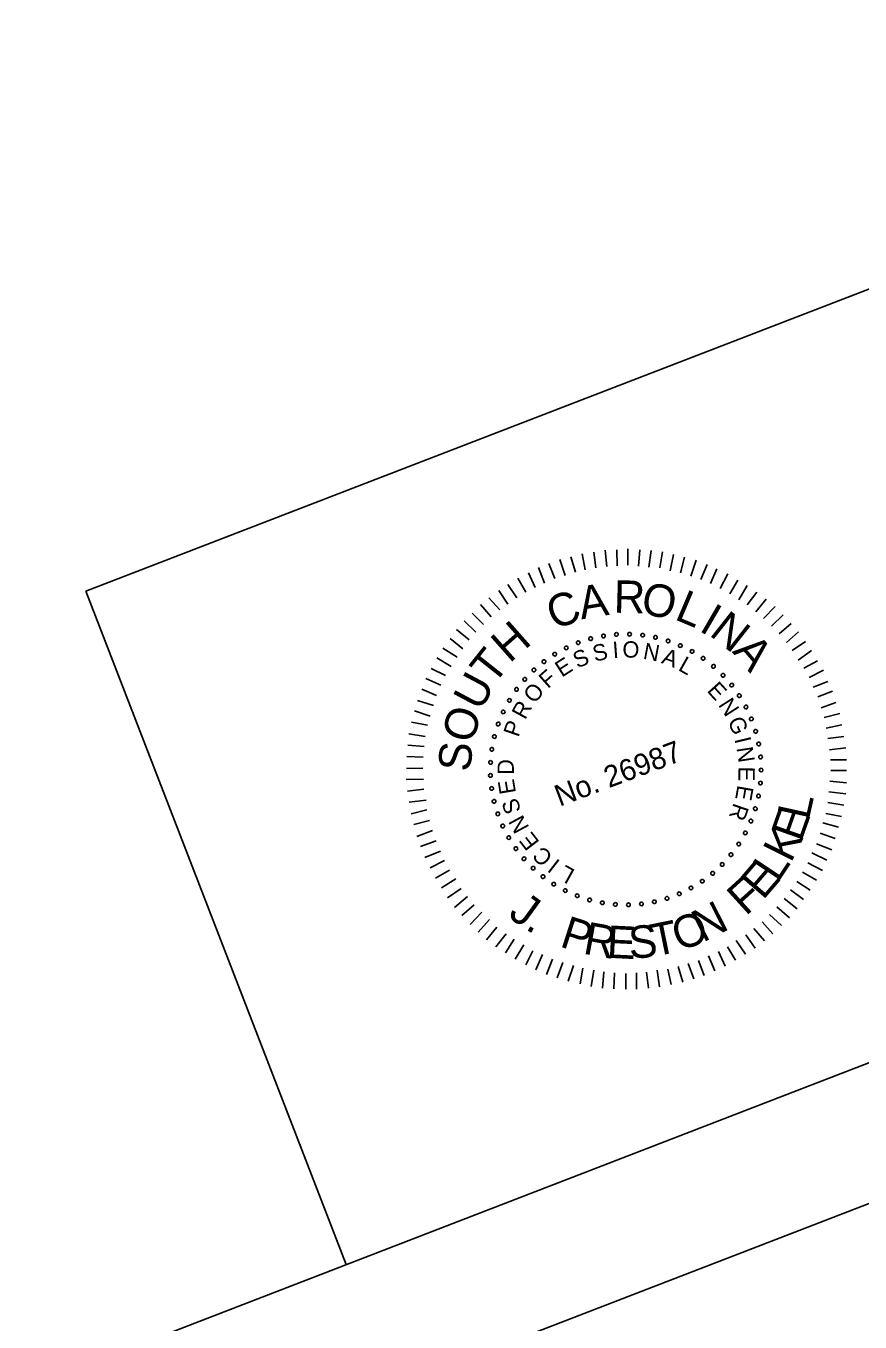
# Model space of a CAD drawing. Extents: x 1971188 to 1971603, y 795903 to 796238.
# Drawn here: x 1971464.12 to 1971495.88, y 795987.28 to 796036.66 of the extents above; entities that cross this region are included whole.
import ezdxf

# ---------------------------------------------------------------- set-up
doc = ezdxf.new("R2010")
doc.units = 0
for name, color, linetype in [('BR_BORDER LINES', 7, 'Continuous'), ('BR_TEXT', 7, 'Continuous'), ('Level 31', 7, 'Continuous')]:
    doc.layers.add(name, color=color, linetype=linetype)

msp = doc.modelspace()

# ---------------------------------------------------------------- linework, layer by layer
at = {"layer": 'BR_BORDER LINES'}
for p, q in [((1971282.272, 795914.531), (1971596.323, 796035.824)), ((1971466.4, 796015.126), (1971516.449, 796034.456)), ((1971476.308, 795989.472), (1971466.4, 796015.126))]:
    msp.add_line(p, q, dxfattribs=at)
at = {"layer": 'BR_TEXT'}
for p, q in [((1971485.419, 796015.944), (1971485.301, 796016.551)), ((1971485.824, 796016.014), (1971485.744, 796016.617)), ((1971486.245, 796016.063), (1971486.176, 796016.687)), ((1971486.627, 796016.097), (1971486.625, 796016.71)), ((1971487.042, 796016.115), (1971487.037, 796016.737)), ((1971487.44, 796016.082), (1971487.5, 796016.701)), ((1971487.838, 796016.048), (1971487.93, 796016.679)), ((1971488.255, 796016.013), (1971488.361, 796016.631)), ((1971484.254, 796015.606), (1971484.036, 796016.184)), ((1971484.656, 796015.73), (1971484.445, 796016.339)), ((1971485.043, 796015.848), (1971484.868, 796016.433)), ((1971488.653, 796015.906), (1971488.775, 796016.53)), ((1971489.041, 796015.823), (1971489.2, 796016.424)), ((1971489.437, 796015.697), (1971489.639, 796016.305)), ((1971489.822, 796015.576), (1971490.066, 796016.145)), ((1971483.155, 796015.091), (1971482.852, 796015.628)), ((1971483.509, 796015.27), (1971483.254, 796015.825)), ((1971483.869, 796015.434), (1971483.642, 796016.036)), ((1971490.184, 796015.419), (1971490.431, 796015.98)), ((1971490.558, 796015.23), (1971490.851, 796015.79)), ((1971490.927, 796015.03), (1971491.224, 796015.554)), ((1971482.463, 796014.638), (1971482.12, 796015.16)), ((1971482.813, 796014.879), (1971482.467, 796015.382)), ((1971491.27, 796014.801), (1971491.588, 796015.343)), ((1971491.581, 796014.607), (1971491.956, 796015.096)), ((1971481.838, 796014.155), (1971481.432, 796014.625)), ((1971482.162, 796014.415), (1971481.751, 796014.874)), ((1971491.92, 796014.34), (1971492.306, 796014.825)), ((1971481.538, 796013.858), (1971481.116, 796014.295)), ((1971492.21, 796014.082), (1971492.651, 796014.542)), ((1971492.509, 796013.801), (1971492.951, 796014.233)), ((1971480.995, 796013.278), (1971480.515, 796013.675)), ((1971481.253, 796013.567), (1971480.807, 796013.995)), ((1971492.805, 796013.5), (1971493.26, 796013.9)), ((1971493.076, 796013.171), (1971493.536, 796013.582)), ((1971480.75, 796012.929), (1971480.271, 796013.326)), ((1971493.3, 796012.87), (1971493.81, 796013.218)), ((1971480.537, 796012.619), (1971479.989, 796012.954)), ((1971493.528, 796012.506), (1971494.036, 796012.863)), ((1971480.097, 796011.912), (1971479.546, 796012.182)), ((1971480.315, 796012.26), (1971479.762, 796012.584)), ((1971493.736, 796012.199), (1971494.262, 796012.481)), ((1971493.945, 796011.838), (1971494.491, 796012.117)), ((1971479.921, 796011.553), (1971479.349, 796011.805)), ((1971494.1, 796011.475), (1971494.662, 796011.687)), ((1971479.757, 796011.16), (1971479.199, 796011.4)), ((1971494.269, 796011.099), (1971494.839, 796011.314)), ((1971479.636, 796010.776), (1971479.034, 796010.962)), ((1971494.397, 796010.688), (1971494.965, 796010.884)), ((1971479.415, 796010.023), (1971478.794, 796010.138)), ((1971479.513, 796010.372), (1971478.908, 796010.566)), ((1971494.517, 796010.32), (1971495.114, 796010.463)), ((1971479.32, 796009.593), (1971478.703, 796009.7)), ((1971494.598, 796009.911), (1971495.185, 796010.031)), ((1971479.281, 796009.211), (1971478.654, 796009.268)), ((1971494.657, 796009.511), (1971495.267, 796009.595)), ((1971494.725, 796009.087), (1971495.338, 796009.163)), ((1971479.25, 796008.805), (1971478.624, 796008.836)), ((1971494.758, 796008.706), (1971495.372, 796008.708)), ((1971479.226, 796008.383), (1971478.604, 796008.379)), ((1971494.766, 796008.296), (1971495.372, 796008.295)), ((1971479.255, 796007.964), (1971478.599, 796007.955)), ((1971494.735, 796007.89), (1971495.362, 796007.833)), ((1971479.27, 796007.584), (1971478.648, 796007.506)), ((1971479.354, 796007.166), (1971478.714, 796007.09)), ((1971494.694, 796007.489), (1971495.338, 796007.411)), ((1971479.385, 796006.793), (1971478.787, 796006.65)), ((1971494.655, 796007.081), (1971495.265, 796006.971)), ((1971479.49, 796006.392), (1971478.888, 796006.239)), ((1971494.471, 796006.305), (1971495.059, 796006.132)), ((1971494.576, 796006.656), (1971495.178, 796006.544)), ((1971479.605, 796006.014), (1971479.003, 796005.787)), ((1971494.364, 796005.907), (1971494.937, 796005.701)), ((1971479.734, 796005.622), (1971479.148, 796005.402)), ((1971479.901, 796005.227), (1971479.305, 796004.984)), ((1971494.225, 796005.497), (1971494.812, 796005.278)), ((1971480.062, 796004.874), (1971479.511, 796004.585)), ((1971493.892, 796004.775), (1971494.456, 796004.493)), ((1971494.051, 796005.156), (1971494.613, 796004.882)), ((1971480.247, 796004.504), (1971479.71, 796004.201)), ((1971493.685, 796004.423), (1971494.229, 796004.123)), ((1971480.483, 796004.171), (1971479.945, 796003.822)), ((1971480.695, 796003.802), (1971480.176, 796003.45)), ((1971493.233, 796003.748), (1971493.731, 796003.376)), ((1971493.471, 796004.067), (1971493.978, 796003.744)), ((1971480.938, 796003.499), (1971480.435, 796003.08)), ((1971492.999, 796003.421), (1971493.486, 796003.027)), ((1971481.186, 796003.18), (1971480.716, 796002.773)), ((1971481.477, 796002.895), (1971481.036, 796002.436)), ((1971492.438, 796002.816), (1971492.892, 796002.39)), ((1971492.715, 796003.103), (1971493.201, 796002.69)), ((1971481.765, 796002.618), (1971481.341, 796002.138)), ((1971482.055, 796002.333), (1971481.662, 796001.846)), ((1971491.834, 796002.276), (1971492.241, 796001.806)), ((1971492.161, 796002.528), (1971492.562, 796002.073)), ((1971482.41, 796002.073), (1971482.016, 796001.585)), ((1971482.714, 796001.875), (1971482.379, 796001.355)), ((1971491.17, 796001.824), (1971491.516, 796001.294)), ((1971491.531, 796002.034), (1971491.885, 796001.534)), ((1971483.073, 796001.653), (1971482.746, 796001.108)), ((1971483.424, 796001.428), (1971483.159, 796000.888)), ((1971483.788, 796001.289), (1971483.531, 796000.707)), ((1971490.117, 796001.235), (1971490.351, 796000.663)), ((1971490.486, 796001.401), (1971490.744, 796000.838)), ((1971490.832, 796001.577), (1971491.134, 796001.068)), ((1971484.166, 796001.111), (1971483.936, 796000.53)), ((1971484.563, 796000.986), (1971484.352, 796000.401)), ((1971484.967, 796000.862), (1971484.767, 796000.274)), ((1971485.331, 796000.77), (1971485.227, 796000.172)), ((1971488.952, 796000.824), (1971489.13, 796000.23)), ((1971489.331, 796000.939), (1971489.548, 796000.36)), ((1971489.733, 796001.063), (1971489.948, 796000.492)), ((1971485.739, 796000.686), (1971485.641, 796000.071)), ((1971486.13, 796000.622), (1971486.078, 796000.006)), ((1971486.536, 796000.592), (1971486.508, 795999.985)), ((1971486.957, 796000.567), (1971486.957, 795999.962)), ((1971487.369, 796000.594), (1971487.366, 795999.969)), ((1971487.749, 796000.609), (1971487.829, 796000.006)), ((1971488.159, 796000.69), (1971488.24, 796000.06)), ((1971488.567, 796000.724), (1971488.685, 796000.145))]:
    msp.add_line(p, q, dxfattribs=at)
for centre, start, end in [((1971485.15, 796013.166), 20.6445, 200.6445), ((1971485.15, 796013.166), 200.6445, 20.6445), ((1971485.625, 796013.318), 15.1061, 195.1061), ((1971485.625, 796013.318), 195.1061, 15.1061), ((1971486.112, 796013.423), 9.5676, 189.5676), ((1971486.112, 796013.423), 189.5676, 9.5676), ((1971486.607, 796013.481), 4.0291, 184.0291), ((1971486.607, 796013.481), 184.0291, 4.0291), ((1971487.105, 796013.491), 358.4907, 178.4907), ((1971487.105, 796013.491), 178.4907, 358.4907), ((1971487.602, 796013.453), 352.9522, 172.9522), ((1971487.602, 796013.453), 172.9522, 352.9522), ((1971488.092, 796013.367), 167.4138, 347.4138), ((1971488.092, 796013.367), 347.4138, 167.4138), ((1971488.573, 796013.234), 161.8753, 341.8753), ((1971488.573, 796013.234), 341.8753, 161.8753), ((1971489.038, 796013.055), 156.3368, 336.3368), ((1971489.038, 796013.055), 336.3368, 156.3368), ((1971484.256, 796012.728), 31.7214, 211.7214), ((1971484.256, 796012.728), 211.7214, 31.7214), ((1971484.692, 796012.969), 26.183, 206.183), ((1971484.692, 796012.969), 206.183, 26.183), ((1971489.484, 796012.833), 150.7984, 330.7984), ((1971489.484, 796012.833), 330.7984, 150.7984), ((1971489.906, 796012.568), 145.2599, 325.2599), ((1971489.906, 796012.568), 325.2599, 145.2599), ((1971483.462, 796012.127), 42.7984, 222.7984), ((1971483.462, 796012.127), 222.7984, 42.7984), ((1971483.845, 796012.447), 37.2599, 217.2599), ((1971483.845, 796012.447), 217.2599, 37.2599), ((1971490.301, 796012.264), 139.7214, 319.7214), ((1971490.301, 796012.264), 319.7214, 139.7214), ((1971483.113, 796011.772), 48.3368, 228.3368), ((1971483.113, 796011.772), 228.3368, 48.3368), ((1971490.664, 796011.923), 134.183, 314.183), ((1971490.664, 796011.923), 314.183, 134.183), ((1971490.993, 796011.549), 128.6445, 308.6445), ((1971490.993, 796011.549), 308.6445, 128.6445), ((1971482.799, 796011.385), 53.8753, 233.8753), ((1971482.799, 796011.385), 233.8753, 53.8753), ((1971491.284, 796011.144), 123.1061, 303.1061), ((1971491.284, 796011.144), 303.1061, 123.1061), ((1971482.524, 796010.969), 59.4138, 239.4138), ((1971482.524, 796010.969), 239.4138, 59.4138), ((1971491.535, 796010.714), 117.5676, 297.5676), ((1971491.535, 796010.714), 297.5676, 117.5676), ((1971482.101, 796010.068), 70.4907, 250.4907), ((1971482.101, 796010.068), 250.4907, 70.4907), ((1971482.291, 796010.529), 64.9522, 244.9522), ((1971482.291, 796010.529), 244.9522, 64.9522), ((1971491.743, 796010.261), 112.0291, 292.0291), ((1971491.743, 796010.261), 292.0291, 112.0291), ((1971481.957, 796009.591), 76.0291, 256.0291), ((1971481.957, 796009.591), 256.0291, 76.0291), ((1971491.907, 796009.79), 106.4907, 286.4907), ((1971491.907, 796009.79), 286.4907, 106.4907), ((1971481.859, 796009.103), 81.5676, 261.5676), ((1971481.859, 796009.103), 261.5676, 81.5676), ((1971492.024, 796009.306), 100.9522, 280.9522), ((1971492.024, 796009.306), 280.9522, 100.9522), ((1971481.809, 796008.607), 87.1061, 267.1061), ((1971481.809, 796008.607), 267.1061, 87.1061), ((1971492.094, 796008.813), 95.4138, 275.4138), ((1971492.094, 796008.813), 275.4138, 95.4138), ((1971481.807, 796008.108), 92.6445, 272.6445), ((1971481.807, 796008.108), 272.6445, 92.6445), ((1971492.116, 796008.315), 89.8753, 269.8753), ((1971492.116, 796008.315), 269.8753, 89.8753), ((1971481.853, 796007.612), 98.183, 278.183), ((1971481.853, 796007.612), 278.183, 98.183), ((1971492.09, 796007.817), 84.3368, 264.3368), ((1971492.09, 796007.817), 264.3368, 84.3368), ((1971481.946, 796007.123), 103.7214, 283.7214), ((1971481.946, 796007.123), 283.7214, 103.7214), ((1971492.016, 796007.324), 78.7984, 258.7984), ((1971492.016, 796007.324), 258.7984, 78.7984), ((1971482.087, 796006.645), 109.2599, 289.2599), ((1971482.087, 796006.645), 289.2599, 109.2599), ((1971491.894, 796006.841), 73.2599, 253.2599), ((1971491.894, 796006.841), 253.2599, 73.2599), ((1971482.273, 796006.182), 114.7984, 294.7984), ((1971482.273, 796006.182), 294.7984, 114.7984), ((1971491.727, 796006.372), 67.7214, 247.7214), ((1971491.727, 796006.372), 247.7214, 67.7214), ((1971482.503, 796005.74), 120.3368, 300.3368), ((1971482.503, 796005.74), 300.3368, 120.3368), ((1971491.515, 796005.921), 62.183, 242.183), ((1971491.515, 796005.921), 242.183, 62.183), ((1971482.774, 796005.322), 125.8753, 305.8753), ((1971482.774, 796005.322), 305.8753, 125.8753), ((1971491.261, 796005.492), 56.6445, 236.6445), ((1971491.261, 796005.492), 236.6445, 56.6445), ((1971483.084, 796004.933), 131.4138, 311.4138), ((1971483.084, 796004.933), 311.4138, 131.4138), ((1971490.634, 796004.719), 45.5676, 225.5676), ((1971490.634, 796004.719), 225.5676, 45.5676), ((1971490.966, 796005.09), 51.1061, 231.1061), ((1971490.966, 796005.09), 231.1061, 51.1061), ((1971483.431, 796004.574), 136.9522, 316.9522), ((1971483.431, 796004.574), 316.9522, 136.9522), ((1971483.811, 796004.252), 142.4907, 322.4907), ((1971483.811, 796004.252), 322.4907, 142.4907), ((1971490.268, 796004.381), 40.0291, 220.0291), ((1971490.268, 796004.381), 220.0291, 40.0291), ((1971484.219, 796003.967), 148.0291, 328.0291), ((1971484.219, 796003.967), 328.0291, 148.0291), ((1971484.654, 796003.723), 153.5676, 333.5676), ((1971484.654, 796003.723), 333.5676, 153.5676), ((1971489.446, 796003.819), 28.9522, 208.9522), ((1971489.446, 796003.819), 208.9522, 28.9522), ((1971489.871, 796004.08), 34.4907, 214.4907), ((1971489.871, 796004.08), 214.4907, 34.4907), ((1971485.11, 796003.522), 159.1061, 339.1061), ((1971485.11, 796003.522), 339.1061, 159.1061), ((1971485.583, 796003.366), 164.6445, 344.6445), ((1971485.583, 796003.366), 344.6445, 164.6445), ((1971486.069, 796003.256), 170.183, 350.183), ((1971486.069, 796003.256), 350.183, 170.183), ((1971486.564, 796003.194), 355.7214, 175.7214), ((1971487.062, 796003.18), 1.2599, 181.2599), ((1971487.559, 796003.214), 6.7984, 186.7984), ((1971487.559, 796003.214), 186.7984, 6.7984), ((1971488.051, 796003.296), 12.3368, 192.3368), ((1971488.051, 796003.296), 192.3368, 12.3368), ((1971488.532, 796003.425), 17.8753, 197.8753), ((1971488.532, 796003.425), 197.8753, 17.8753), ((1971488.999, 796003.6), 23.4138, 203.4138), ((1971488.999, 796003.6), 203.4138, 23.4138), ((1971486.564, 796003.194), 175.7214, 355.7214), ((1971487.062, 796003.18), 181.2599, 1.2599)]:
    msp.add_arc(centre, 0.0701, start, end, dxfattribs=at)
at = {"layer": 'Level 31'}
msp.add_lwpolyline([(1971266.971, 795903.262), (1971602.794, 796032.965), (1971523.531, 796238.19), (1971187.708, 796108.487)], close=True, dxfattribs=at)

# ---------------------------------------------------------------- texts
at = {"layer": 'BR_TEXT'}
for s, height, rotation, p in [('C', 1.241, 20.6659, (1971484.232, 796013.643)), ('A', 1.241, 9.3158, (1971485.268, 796014.052)), ('R', 1.241, 358.5521, (1971486.49, 796014.31)), ('O', 1.239, 347.7046, (1971487.483, 796014.3)), ('L', 1.241, 337.0665, (1971488.777, 796014.073)), ('I', 1.241, 329.779, (1971489.71, 796013.637)), ('N', 1.241, 321.8213, (1971490.102, 796013.473)), ('H', 1.241, 41.4814, (1971482.535, 796012.362)), ('S', 0.622, 13.7785, (1971485.783, 796012.433)), ('I', 0.622, 4.2313, (1971486.481, 796012.574)), ('O', 0.622, 359.5569, (1971486.83, 796012.6)), ('N', 0.622, 349.3218, (1971487.592, 796012.558)), ('A', 1.241, 310.5969, (1971490.989, 796012.819)), ('T', 1.241, 51.6169, (1971481.922, 796011.509)), ('E', 0.622, 32.528, (1971484.524, 796011.831)), ('S', 0.622, 23.3257, (1971485.117, 796012.178)), ('A', 0.622, 339.7747, (1971488.287, 796012.397)), ('L', 0.622, 330.5723, (1971488.922, 796012.135)), ('F', 0.622, 41.7304, (1971483.994, 796011.394)), ('U', 1.241, 61.9199, (1971481.434, 796010.519)), ('E', 0.622, 312.1667, (1971490.026, 796011.325)), ('O', 0.622, 51.9654, (1971483.496, 796010.816)), ('O', 1.241, 73.1444, (1971481.113, 796009.281)), ('R', 0.622, 61.5126, (1971483.13, 796010.204)), ('N', 0.622, 302.9643, (1971490.467, 796010.799)), ('P', 0.622, 71.0598, (1971482.871, 796009.54)), ('G', 0.622, 293.4172, (1971490.83, 796010.185)), ('S', 1.239, 84.3688, (1971481.035, 796008.226)), ('No. 26987', 0.8175, 20.6445, (1971484.441, 796006.915)), ('I', 0.622, 283.526, (1971491.093, 796009.495)), ('N', 0.622, 278.8516, (1971491.175, 796009.156)), ('D', 0.622, 90.1541, (1971482.698, 796008.13)), ('E', 0.622, 269.3044, (1971491.255, 796008.448)), ('E', 0.622, 99.3565, (1971482.783, 796007.449)), ('E', 0.622, 260.1021, (1971491.221, 796007.762)), ('S', 0.622, 108.9037, (1971482.986, 796006.765)), ('L', 1.236, 77.5424, (1971493.931, 796006.386)), ('R', 0.622, 250.8997, (1971491.077, 796007.09)), ('E', 1.236, 70.4816, (1971493.639, 796005.547)), ('N', 0.622, 118.4508, (1971483.299, 796006.125)), ('K', 1.236, 63.4208, (1971493.246, 796004.751)), ('E', 0.622, 127.6532, (1971483.698, 796005.566)), ('C', 0.622, 137.5443, (1971484.22, 796005.043)), ('I', 0.622, 142.2188, (1971484.496, 796004.83)), ('L', 0.622, 151.0772, (1971485.063, 796004.49)), ('E', 1.236, 49.2991, (1971492.183, 796003.332)), ('L', 1.236, 56.3599, (1971492.758, 796004.009)), ('F', 1.236, 42.2383, (1971491.529, 796002.732)), ('J', 1.236, 324.0736, (1971482.438, 796002.742)), ('N', 1.236, 26.9398, (1971489.89, 796001.733)), ('P', 1.236, 342.2212, (1971484.406, 796001.602)), ('O', 1.236, 19.2596, (1971488.982, 796001.404)), ('.', 1.236, 330.515, (1971483.094, 796002.266)), ('R', 1.236, 349.6536, (1971485.298, 796001.325)), ('E', 1.236, 357.0861, (1971486.219, 796001.165)), ('S', 1.236, 4.1469, (1971487.106, 796001.124)), ('T', 1.236, 11.5794, (1971488.038, 796001.2))]:
    msp.add_text(s, height=height, rotation=rotation, dxfattribs=at).set_placement(p)

doc.saveas('drawing.dxf')
